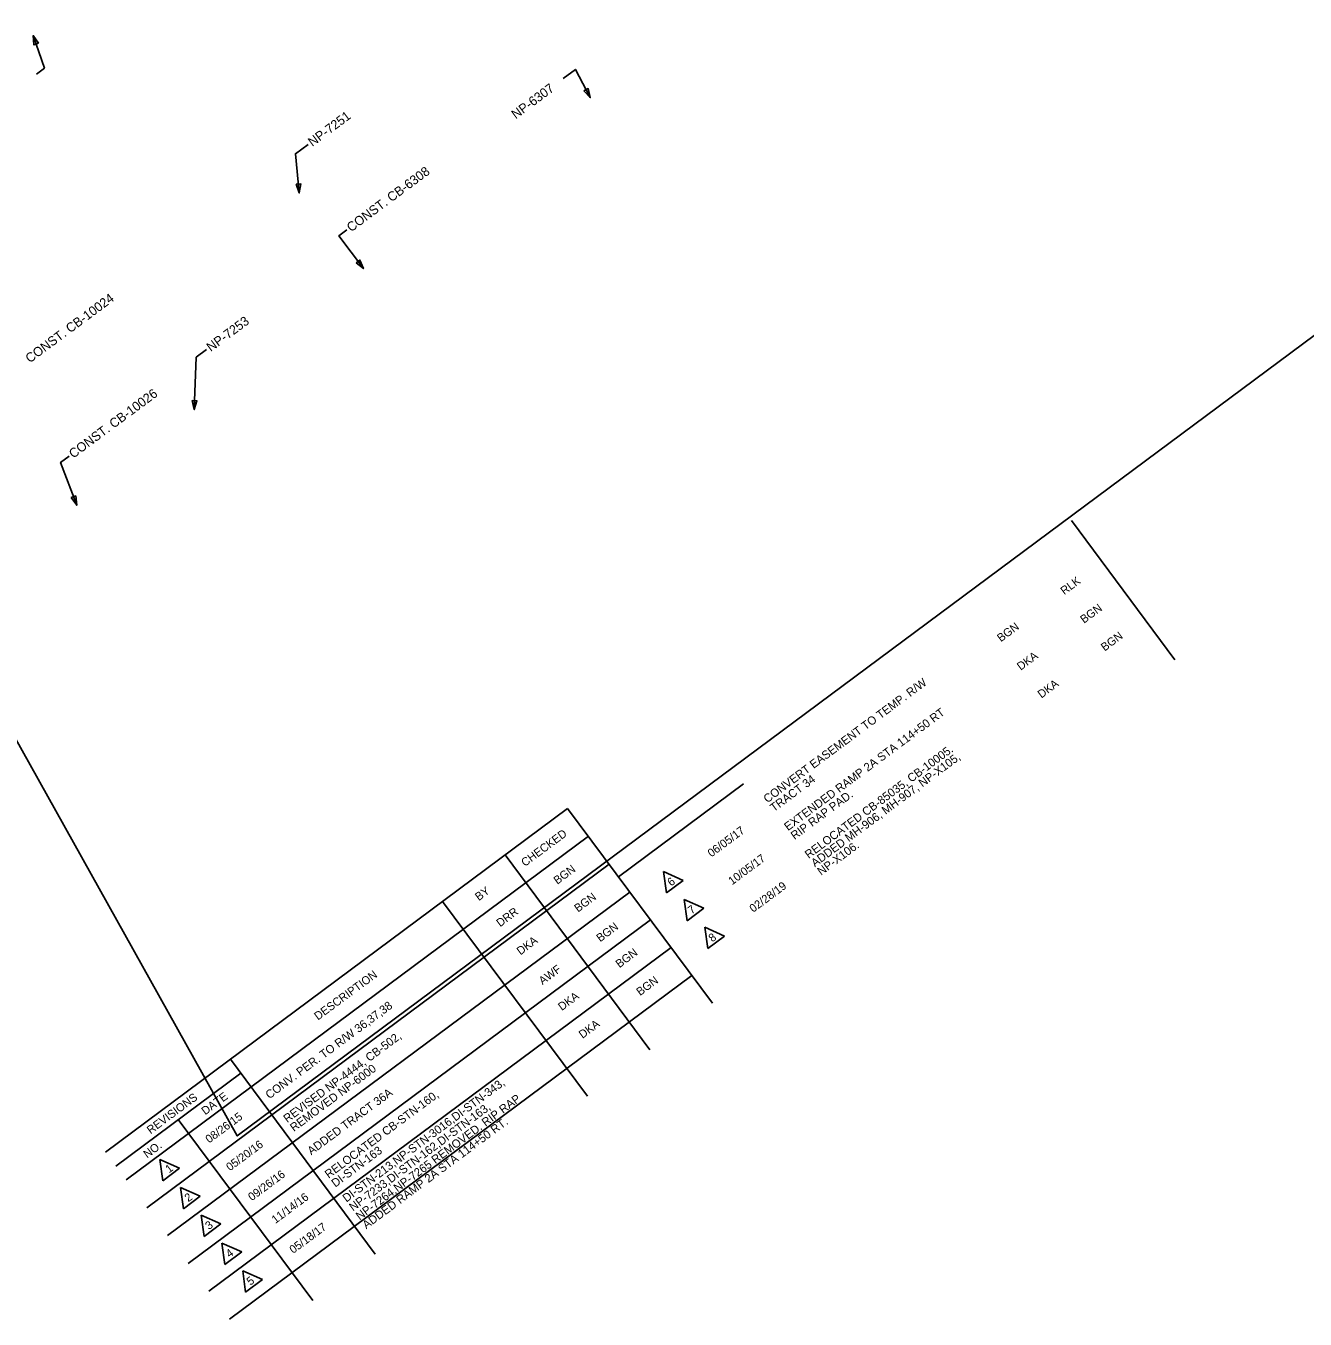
# Model space of a CAD drawing. Extents: x 1612334 to 1614149, y 1094755 to 1096548.
# Drawn here: x 1612754 to 1613444, y 1094755 to 1095452 of the extents above; entities that cross this region are included whole.
import ezdxf

# ---------------------------------------------------------------- set-up
doc = ezdxf.new("R2010")
doc.units = 0
for name, color, linetype in [('Level 15', 7, 'Continuous'), ('Level 29', 7, 'Continuous'), ('RD_HY_DumbNodes', 7, 'Continuous')]:
    doc.layers.add(name, color=color, linetype=linetype)

msp = doc.modelspace()

# ---------------------------------------------------------------- linework, layer by layer
at = {"layer": 'Level 15'}
msp.add_lwpolyline([(1612485.6, 1095458.44), (1612588.44, 1095320.1), (1612593.04, 1095313.91), (1612580.15, 1095304.29), (1612634.52, 1095231.15), (1612645.51, 1095216.31), (1612653.41, 1095198.54), (1612742.51, 1095078.69), (1612867.99, 1094853.86), (1614076.24, 1095752.03), (1613959.14, 1095956.14), (1613849.89, 1096103.11), (1613853.42, 1096105.74), (1613781.72, 1096202.21), (1613794.63, 1096211.8), (1613636.52, 1096424.5), (1613567.38, 1096517.5), (1613431.61, 1096416.58), (1613412.2, 1096442.69), (1612334.44, 1095641.53)], close=True, dxfattribs=at)
msp.add_lwpolyline([(1612485.6, 1095458.44), (1612588.44, 1095320.1), (1612593.04, 1095313.91), (1612580.15, 1095304.29), (1612634.52, 1095231.15), (1612645.51, 1095216.31), (1612653.41, 1095198.54), (1612742.51, 1095078.69), (1612867.99, 1094853.86), (1614076.24, 1095752.03), (1613959.14, 1095956.14), (1613849.89, 1096103.11), (1613853.42, 1096105.74), (1613781.72, 1096202.21), (1613794.63, 1096211.8), (1613636.52, 1096424.5), (1613567.38, 1096517.5), (1613431.61, 1096416.58), (1613412.2, 1096442.69), (1612334.44, 1095641.53)], close=True, dxfattribs=at)
msp.add_lwpolyline([(1612485.6, 1095458.44), (1612588.44, 1095320.1), (1612593.04, 1095313.91), (1612580.15, 1095304.29), (1612634.52, 1095231.15), (1612645.51, 1095216.31), (1612653.41, 1095198.54), (1612742.51, 1095078.69), (1612867.99, 1094853.86), (1614076.24, 1095752.03), (1613959.14, 1095956.14), (1613849.89, 1096103.11), (1613853.42, 1096105.74), (1613781.72, 1096202.21), (1613794.63, 1096211.8), (1613636.52, 1096424.5), (1613567.38, 1096517.5), (1613431.61, 1096416.58), (1613412.2, 1096442.69), (1612334.44, 1095641.53)], close=True, dxfattribs=at)
msp.add_lwpolyline([(1612485.6, 1095458.44), (1612588.44, 1095320.1), (1612593.04, 1095313.91), (1612580.15, 1095304.29), (1612634.52, 1095231.15), (1612645.51, 1095216.31), (1612653.41, 1095198.54), (1612742.51, 1095078.69), (1612867.99, 1094853.86), (1614076.24, 1095752.03), (1613959.14, 1095956.14), (1613849.89, 1096103.11), (1613853.42, 1096105.74), (1613781.72, 1096202.21), (1613794.63, 1096211.8), (1613636.52, 1096424.5), (1613567.38, 1096517.5), (1613431.61, 1096416.58), (1613412.2, 1096442.69), (1612334.44, 1095641.53)], close=True, dxfattribs=at)
msp.add_lwpolyline([(1612485.6, 1095458.44), (1612588.44, 1095320.1), (1612593.04, 1095313.91), (1612580.15, 1095304.29), (1612634.52, 1095231.15), (1612645.51, 1095216.31), (1612653.41, 1095198.54), (1612742.51, 1095078.69), (1612867.99, 1094853.86), (1614076.24, 1095752.03), (1613959.14, 1095956.14), (1613849.89, 1096103.11), (1613853.42, 1096105.74), (1613781.72, 1096202.21), (1613794.63, 1096211.8), (1613636.52, 1096424.5), (1613567.38, 1096517.5), (1613431.61, 1096416.58), (1613412.2, 1096442.69), (1612334.44, 1095641.53)], close=True, dxfattribs=at)
msp.add_lwpolyline([(1612485.6, 1095458.44), (1612588.44, 1095320.1), (1612593.04, 1095313.91), (1612580.15, 1095304.29), (1612634.52, 1095231.15), (1612645.51, 1095216.31), (1612653.41, 1095198.54), (1612742.51, 1095078.69), (1612867.99, 1094853.86), (1614076.24, 1095752.03), (1613959.14, 1095956.14), (1613849.89, 1096103.11), (1613853.42, 1096105.74), (1613781.72, 1096202.21), (1613794.63, 1096211.8), (1613636.52, 1096424.5), (1613567.38, 1096517.5), (1613431.61, 1096416.58), (1613412.2, 1096442.69), (1612334.44, 1095641.53)], close=True, dxfattribs=at)
msp.add_lwpolyline([(1612485.6, 1095458.44), (1612588.44, 1095320.1), (1612593.04, 1095313.91), (1612580.15, 1095304.29), (1612634.52, 1095231.15), (1612645.51, 1095216.31), (1612653.41, 1095198.54), (1612742.51, 1095078.69), (1612867.99, 1094853.86), (1614076.24, 1095752.03), (1613959.14, 1095956.14), (1613849.89, 1096103.11), (1613853.42, 1096105.74), (1613781.72, 1096202.21), (1613794.63, 1096211.8), (1613636.52, 1096424.5), (1613567.38, 1096517.5), (1613431.61, 1096416.58), (1613412.2, 1096442.69), (1612334.44, 1095641.53)], close=True, dxfattribs=at)
msp.add_lwpolyline([(1612485.6, 1095458.44), (1612588.44, 1095320.1), (1612593.04, 1095313.91), (1612580.15, 1095304.29), (1612634.52, 1095231.15), (1612645.51, 1095216.31), (1612653.41, 1095198.54), (1612742.51, 1095078.69), (1612867.99, 1094853.86), (1614076.24, 1095752.03), (1613959.14, 1095956.14), (1613849.89, 1096103.11), (1613853.42, 1096105.74), (1613781.72, 1096202.21), (1613794.63, 1096211.8), (1613636.52, 1096424.5), (1613567.38, 1096517.5), (1613431.61, 1096416.58), (1613412.2, 1096442.69), (1612334.44, 1095641.53)], close=True, dxfattribs=at)
at = {"layer": 'Level 29'}
for p, q in [((1613373.54, 1095110.63), (1613317.76, 1095185.67)), ((1613073.59, 1094993.5), (1613141.01, 1095043.61)), ((1612796.9, 1094845.09), (1613046.17, 1095030.39)), ((1613124.26, 1094925.33), (1613046.17, 1095030.38)), ((1613057.33, 1095015.38), (1612808.05, 1094830.08)), ((1613090.56, 1094900.28), (1613012.46, 1095005.33)), ((1613068.48, 1095000.37), (1612819.21, 1094815.07)), ((1613108.52, 1094991.64), (1613097.9, 1094996.39)), ((1613097.9, 1094996.39), (1613099.38, 1094984.85)), ((1613099.38, 1094984.85), (1613108.52, 1094991.64)), ((1613079.64, 1094985.36), (1612830.37, 1094800.06)), ((1613056.85, 1094875.22), (1612978.76, 1094980.27)), ((1613119.68, 1094976.63), (1613109.05, 1094981.38)), ((1613109.05, 1094981.38), (1613110.54, 1094969.84)), ((1613110.54, 1094969.84), (1613119.68, 1094976.63)), ((1613090.8, 1094970.36), (1612841.52, 1094785.06)), ((1613130.83, 1094961.63), (1613120.21, 1094966.37)), ((1613120.21, 1094966.37), (1613121.69, 1094954.83)), ((1613121.69, 1094954.83), (1613130.83, 1094961.63)), ((1613101.95, 1094955.35), (1612852.68, 1094770.05)), ((1613113.11, 1094940.34), (1612863.84, 1094755.04)), ((1612942.41, 1094790.15), (1612864.31, 1094895.2)), ((1612869.89, 1094887.7), (1612802.48, 1094837.58)), ((1612908.7, 1094765.09), (1612836.18, 1094862.64)), ((1612836.94, 1094836.36), (1612826.31, 1094841.11)), ((1612826.31, 1094841.11), (1612827.8, 1094829.56)), ((1612827.8, 1094829.56), (1612836.94, 1094836.36)), ((1612848.09, 1094821.35), (1612837.47, 1094826.1)), ((1612837.47, 1094826.1), (1612838.95, 1094814.56)), ((1612838.95, 1094814.56), (1612848.09, 1094821.35)), ((1612859.25, 1094806.34), (1612848.62, 1094811.09)), ((1612848.62, 1094811.09), (1612850.11, 1094799.55)), ((1612850.11, 1094799.55), (1612859.25, 1094806.34)), ((1612870.4, 1094791.33), (1612859.78, 1094796.08)), ((1612859.78, 1094796.08), (1612861.26, 1094784.54)), ((1612861.26, 1094784.54), (1612870.4, 1094791.33)), ((1612881.56, 1094776.33), (1612870.94, 1094781.07)), ((1612870.94, 1094781.07), (1612872.42, 1094769.53)), ((1612872.42, 1094769.53), (1612881.56, 1094776.33))]:
    msp.add_line(p, q, dxfattribs=at)
at = {"layer": 'RD_HY_DumbNodes'}
for points in [[(1612759.69, 1095426.33), (1612764.08, 1095429.59), (1612758.05, 1095447.15)], [(1613043.73, 1095424.04), (1613050.34, 1095428.95), (1613058.35, 1095413.73)], [(1612906.21, 1095388.48), (1612899.41, 1095383.42), (1612901.45, 1095362.35)], [(1612927.09, 1095342.43), (1612922.82, 1095339.26), (1612936.01, 1095321.48)], [(1612851.48, 1095277.87), (1612845.9, 1095273.72), (1612844.79, 1095245.49)], [(1612777.31, 1095220.37), (1612772.77, 1095217), (1612781.44, 1095193.94)]]:
    msp.add_lwpolyline(points, dxfattribs=at)
for points in [[(1612760.84, 1095443), (1612758.05, 1095447.15), (1612758.39, 1095442.16)], [(1613054.96, 1095417.4), (1613058.35, 1095413.73), (1613057.25, 1095418.61)], [(1612899.7, 1095367.03), (1612901.45, 1095362.35), (1612902.28, 1095367.28)], [(1612932.09, 1095324.59), (1612936.01, 1095321.48), (1612934.17, 1095326.13)], [(1612843.68, 1095250.36), (1612844.79, 1095245.49), (1612846.27, 1095250.26)], [(1612778.53, 1095198), (1612781.44, 1095193.94), (1612780.95, 1095198.91)]]:
    msp.add_lwpolyline(points, close=True, dxfattribs=at)

# ---------------------------------------------------------------- texts
at = {"layer": 'Level 29'}
for s, height, rotation, p in [('RLK', 4.4, 36.62559, (1613313.95, 1095145.38)), ('BGN', 4.4, 36.62559, (1613324.58, 1095129.98)), ('BGN', 4.4, 36.62559, (1613279.76, 1095119.97)), ('BGN', 4.4, 36.62559, (1613335.74, 1095114.98)), ('DKA', 4.4, 36.62559, (1613290.46, 1095104.62)), ('CONVERT EASEMENT TO TEMP. R/W', 4.5, 36.62559, (1613153.83, 1095033.14)), ('DKA', 4.4, 36.62559, (1613301.62, 1095089.61)), ('EXTENDED RAMP 2A STA 114+50 RT', 4.5, 36.62559, (1613164.99, 1095018.13)), ('RELOCATED CB-85035, CB-10005. ', 4.5, 36.62559, (1613176.14, 1095003.12)), ('ADDED MH-906, MH-907, NP-X105,', 4.5, 36.62559, (1613179.5, 1094998.6)), ('TRACT 34', 4.5, 36.62559, (1613157.4, 1095028.33)), ('RIP RAP PAD.', 4.5, 36.62559, (1613168.56, 1095013.33)), ('CHECKED', 4.4, 36.62559, (1613023.12, 1094998.83)), ('06/05/17', 4.4, 36.62559, (1613123.68, 1095003.94)), ('NP-X106.', 4.5, 36.62559, (1613182.86, 1094994.08)), ('10/05/17', 4.4, 36.62559, (1613134.82, 1094988.92)), ('BGN', 4.4, 36.62559, (1613040.61, 1094989.23)), ('6', 4.4, 36.62559, (1613101.95, 1094988.23)), ('02/28/19', 4.4, 36.62559, (1613146.22, 1094974.1)), ('BY', 4.408, 36.35018, (1612998.25, 1094980.39)), ('BGN', 4.4, 36.62559, (1613051.77, 1094974.23)), ('DRR', 4.4, 36.62559, (1613009.75, 1094966.29)), ('7', 4.4, 36.62559, (1613112.99, 1094973.14)), ('BGN', 4.4, 36.62559, (1613063.69, 1094958.18)), ('8', 4.4, 36.62559, (1613124.15, 1094958.13)), ('DKA', 4.4, 36.62559, (1613020.72, 1094951.15)), ('BGN', 4.4, 36.62559, (1613074.08, 1094944.21)), ('DESCRIPTION', 4.4083, 36.35018, (1612911.52, 1094916.01)), ('AWF', 4.4, 36.62559, (1613032.63, 1094935.1)), ('BGN', 4.4, 36.62559, (1613085.23, 1094929.2)), ('DKA', 4.4, 36.62559, (1613043.03, 1094921.13)), ('CONV. PER. TO R/W 36,37,38', 4.5, 36.62559, (1612885.3, 1094873.52)), ('DKA', 4.4, 36.62559, (1613054.19, 1094906.13)), ('REVISED NP-4444, CB-502,', 4.5, 36.62559, (1612894.98, 1094860.72)), ('REMOVED NP-6000', 4.5, 36.62559, (1612898.56, 1094855.92)), ('DATE', 4.408, 36.35018, (1612850.72, 1094864.92)), ('ADDED TRACT 36A', 4.5, 36.62559, (1612907.91, 1094843.33)), ('DI-STN-213,NP-STN-3016,DI-STN-343,', 4.5, 36.62559, (1612926.87, 1094817.83)), ('REVISIONS', 4.4, 36.62559, (1612821.3, 1094854.65)), ('RELOCATED CB-STN-160, ', 4.5, 36.62559, (1612917.3, 1094830.71)), ('NP-7233,DI-STN-162,DI-STN-163,', 4.5, 36.62559, (1612930.44, 1094813.02)), ('NP-7264,NP-7265 REMOVED. RIP RAP', 4.5, 36.62559, (1612934.01, 1094808.21)), ('08/26/15', 4.4, 36.62559, (1612852.9, 1094849.7)), ('ADDED RAMP 2A STA 114+50 RT.', 4.5, 36.62559, (1612937.59, 1094803.41)), ('NO.', 4.4, 36.62559, (1612819.44, 1094841.62)), ('05/20/16', 4.4, 36.62559, (1612864.05, 1094834.69)), ('DI-STN-163', 4.5, 36.62559, (1612920.87, 1094825.9)), ('1', 4.4, 36.62559, (1612831.23, 1094833.59)), ('09/26/16', 4.4, 36.62559, (1612875.89, 1094818.58)), ('2', 4.4, 36.62559, (1612841.61, 1094818)), ('11/14/16', 4.4, 36.62559, (1612888.58, 1094806.32)), ('3', 4.4, 36.62559, (1612852.76, 1094803)), ('05/18/17', 4.4, 36.62559, (1612898.18, 1094790.15)), ('4', 4.4, 36.62559, (1612863.83, 1094787.92)), ('5', 4.4, 36.62559, (1612875.08, 1094772.98))]:
    msp.add_text(s, height=height, rotation=rotation, dxfattribs=at).set_placement(p)
at = {"layer": 'RD_HY_DumbNodes'}
for s, p in [('NP-6307', (1613018.19, 1095401.94)), ('NP-7251', (1612908.51, 1095387.07)), ('CONST. CB-6308', (1612929.39, 1095341.02)), ('CONST. CB-10024', (1612756.15, 1095270.38)), ('NP-7253', (1612853.77, 1095276.46)), ('CONST. CB-10026', (1612779.6, 1095218.96))]:
    msp.add_text(s, height=5, rotation=36.62397, dxfattribs=at).set_placement(p)

doc.saveas('drawing.dxf')
